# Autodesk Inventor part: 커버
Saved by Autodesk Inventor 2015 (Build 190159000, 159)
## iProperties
Created: 2026-07
Part Number: 커버
Material: 일반
Document SubType Name: Modeling
Designer: user
Density: 1 g/cm^3
Appearance: 기본값
Author: user
Author: jhkim
Creation Date: 2026-07-01
Sending System: Autodesk Inventor 2027
Preprocessor: ST-DEVELOPER v20.1
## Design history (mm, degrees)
node "커버1"
node "솔리드1"
node "기준1"
